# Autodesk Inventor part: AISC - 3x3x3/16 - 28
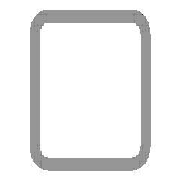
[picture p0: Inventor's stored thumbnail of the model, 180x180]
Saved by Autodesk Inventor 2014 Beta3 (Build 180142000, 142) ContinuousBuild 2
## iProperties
_CCFamilyMember: 9
_CCFamilyDisplayName: ANSI AISC (Square) - Tube
_FrameMemberDoc: Frame Member File
_Version: 15.0.0
_GetPNFromCC: 1
Created: 2011-01
Part Number: AISC - 3x3x3/16 - 28
Material: Steel, Mild
Description: Tube
Document SubType Name: Modeling
Standard: ANSI
Designer: Beta-8540w
Standards Organization: ANSI
Language: en-US
Size Designation: 3x3x3/16
Categories: <MemberInstance><Categories><Category DisplayName="Structural Shapes" InternalName="089c4875-fa83-4c05-b084-43b9cc11f5ed" Mnemonic="GRDR"><CategoryParameter Dis
Stock Number: 3x3x3/16
Density: 7.86 g/cm^3
Appearance: Steel
IsCustomPart: 1
G_L: 28.000 in
G_W: 3.000 in
G_H: 3.000 in
Author: Beta-8540w
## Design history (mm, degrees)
node "Start plane"
node "End plane"
sketch "Sketch"
  geometry: L1 (-38.1, -28.575)-(-38.1, 28.575); L2 (-28.575, 38.1)-(28.575, 38.1); L3 (38.1, 28.575)-(38.1, -28.575); L4 (28.575, -38.1)-(-28.575, -38.1); L5 (-28.575, 33.337)-(28.575, 33.338); L6 (33.338, 28.575)-(33.338, -28.575); L7 (28.575, -33.337)-(-28.575, -33.338); L8 (-33.338, -28.575)-(-33.338, 28.575); L9 (0, 56.102)-(0, -56.102) reference; L10 (-56.102, 0)-(56.102, 0) reference; A1 r 9.525 centre (-28.575, -28.575) between (-38.1, -28.575) and (-28.575, -38.1); A2 r 9.525 centre (-28.575, 28.575) between (-28.575, 38.1) and (-38.1, 28.575); A3 r 9.525 centre (28.575, 28.575) between (38.1, 28.575) and (28.575, 38.1); A4 r 9.525 centre (28.575, -28.575) between (28.575, -38.1) and (38.1, -28.575); A5 r 4.763 centre (-28.575, 28.575) between (-28.575, 33.337) and (-33.338, 28.575); A6 r 4.763 centre (28.575, 28.575) between (33.338, 28.575) and (28.575, 33.338); A7 r 4.763 centre (28.575, -28.575) between (28.575, -33.337) and (33.338, -28.575); A8 r 4.763 centre (-28.575, -28.575) between (-33.338, -28.575) and (-28.575, -33.338)
  constraints: 16 end point, 16 point on circle, 8 centre point, 8 tangent, 4 parallel, 3 equal radius, 2 perpendicular, 7 other
  dimensions: "d10" = 76.2 distance between parallel lines of L2 L4 (= G_H); "d11" = 76.2 distance between parallel lines of L1 L3 (= G_W); "d12" = 4.7625 distance between parallel lines of L3 L6 (= G_T); "d15" = 38.1 distance between parallel lines of L2 L10 (= 0.5 x d10); "d16" = 38.1 distance between parallel lines of L9 L3 (= 0.5 x d11); "d17" = 9.525 radius of A1 (= G_IR)
extrude "Body" new body sketch "Sketch" stored distance "d3" = 711.2 (= G_L); taper "d4" = 0 deg
node "Driven Length"
  sketch "Sketch3"
    geometry: L1 (0, 0)-(10, 0) reference
    constraints: 2 end point, 1 horizontal
  workplane "Work Plane3"
  sketch "Sketch4"
    geometry: L1 (-2, 0)-(12, 0) reference; L2 (-2, 711.2)-(12, 711.2) reference
    dimensions: "d19" = 711.2 distance between parallel lines of L1 L2 (derived)
body "Solid1"
other parameters: "G_W" = 76.2 [user parameter; used in 1 equation term], "G_H" = 76.2 [user parameter; used in 1 equation term], "G_T" = 4.7625 [user parameter; used in 1 equation term], "G_IR" = 9.525 [user parameter; used in 1 equation term], "G_L" = 711.2 (= d19) [user parameter; used in 1 equation term], "G_OFFSET_START" = 0 [user parameter; used in 1 equation term], "G_OFFSET_END" = 0 [user parameter; used in 1 equation term], "d13" = 0 (computed from G_OFFSET_START), "d14" = 711.2 (= G_OFFSET_END + B_L), "B_L" = 711.2 [user parameter; used in 1 equation term], "d18" = 90 deg
